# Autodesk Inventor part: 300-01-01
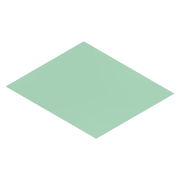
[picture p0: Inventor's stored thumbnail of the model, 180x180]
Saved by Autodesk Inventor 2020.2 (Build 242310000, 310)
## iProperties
Created: 2014-10
Part Number: 300-01-01
Material: Szkło
Document SubType Name: Modeling
Designer: F.Stasiak
Density: 2.18 g/cm^3
Appearance: Przezroczysty - zielony 1
Mass: 3610.08 g
Surface Area: 11129.4 cm^2
Volume: 1656 cm^3
Catalog Web Link: www.expertbooks.pl
Manager: www.cadconsulting.pl
Company: Fabian Stasiak CAD Consulting
Author: F.Stasiak
Subject: Zbiór ćwiczeń. Autodesk Inventor 2020. Kurs Professional
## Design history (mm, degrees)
sketch "Szkic1"
  geometry: L1 (-400, 0)-(400, 0); L2 (400, 0)-(400, 690); L3 (400, 690)-(-400, 690); L4 (-400, 690)-(-400, 0); 2 further points
  constraints: 8 end point, 2 parallel, 1 coincident, 1 horizontal, 1 midpoint, 1 perpendicular
  dimensions: "d0" = 800 distance of L3.end L2.end; "d1" = 690 distance of L2.end L1.end
extrude "Wyciągnięcie proste1" new body sketch "Szkic1" distance "d2" = 3; taper "d3" = 0 deg
node "Bryła1"
